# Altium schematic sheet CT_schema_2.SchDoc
size 401 x 230 mm
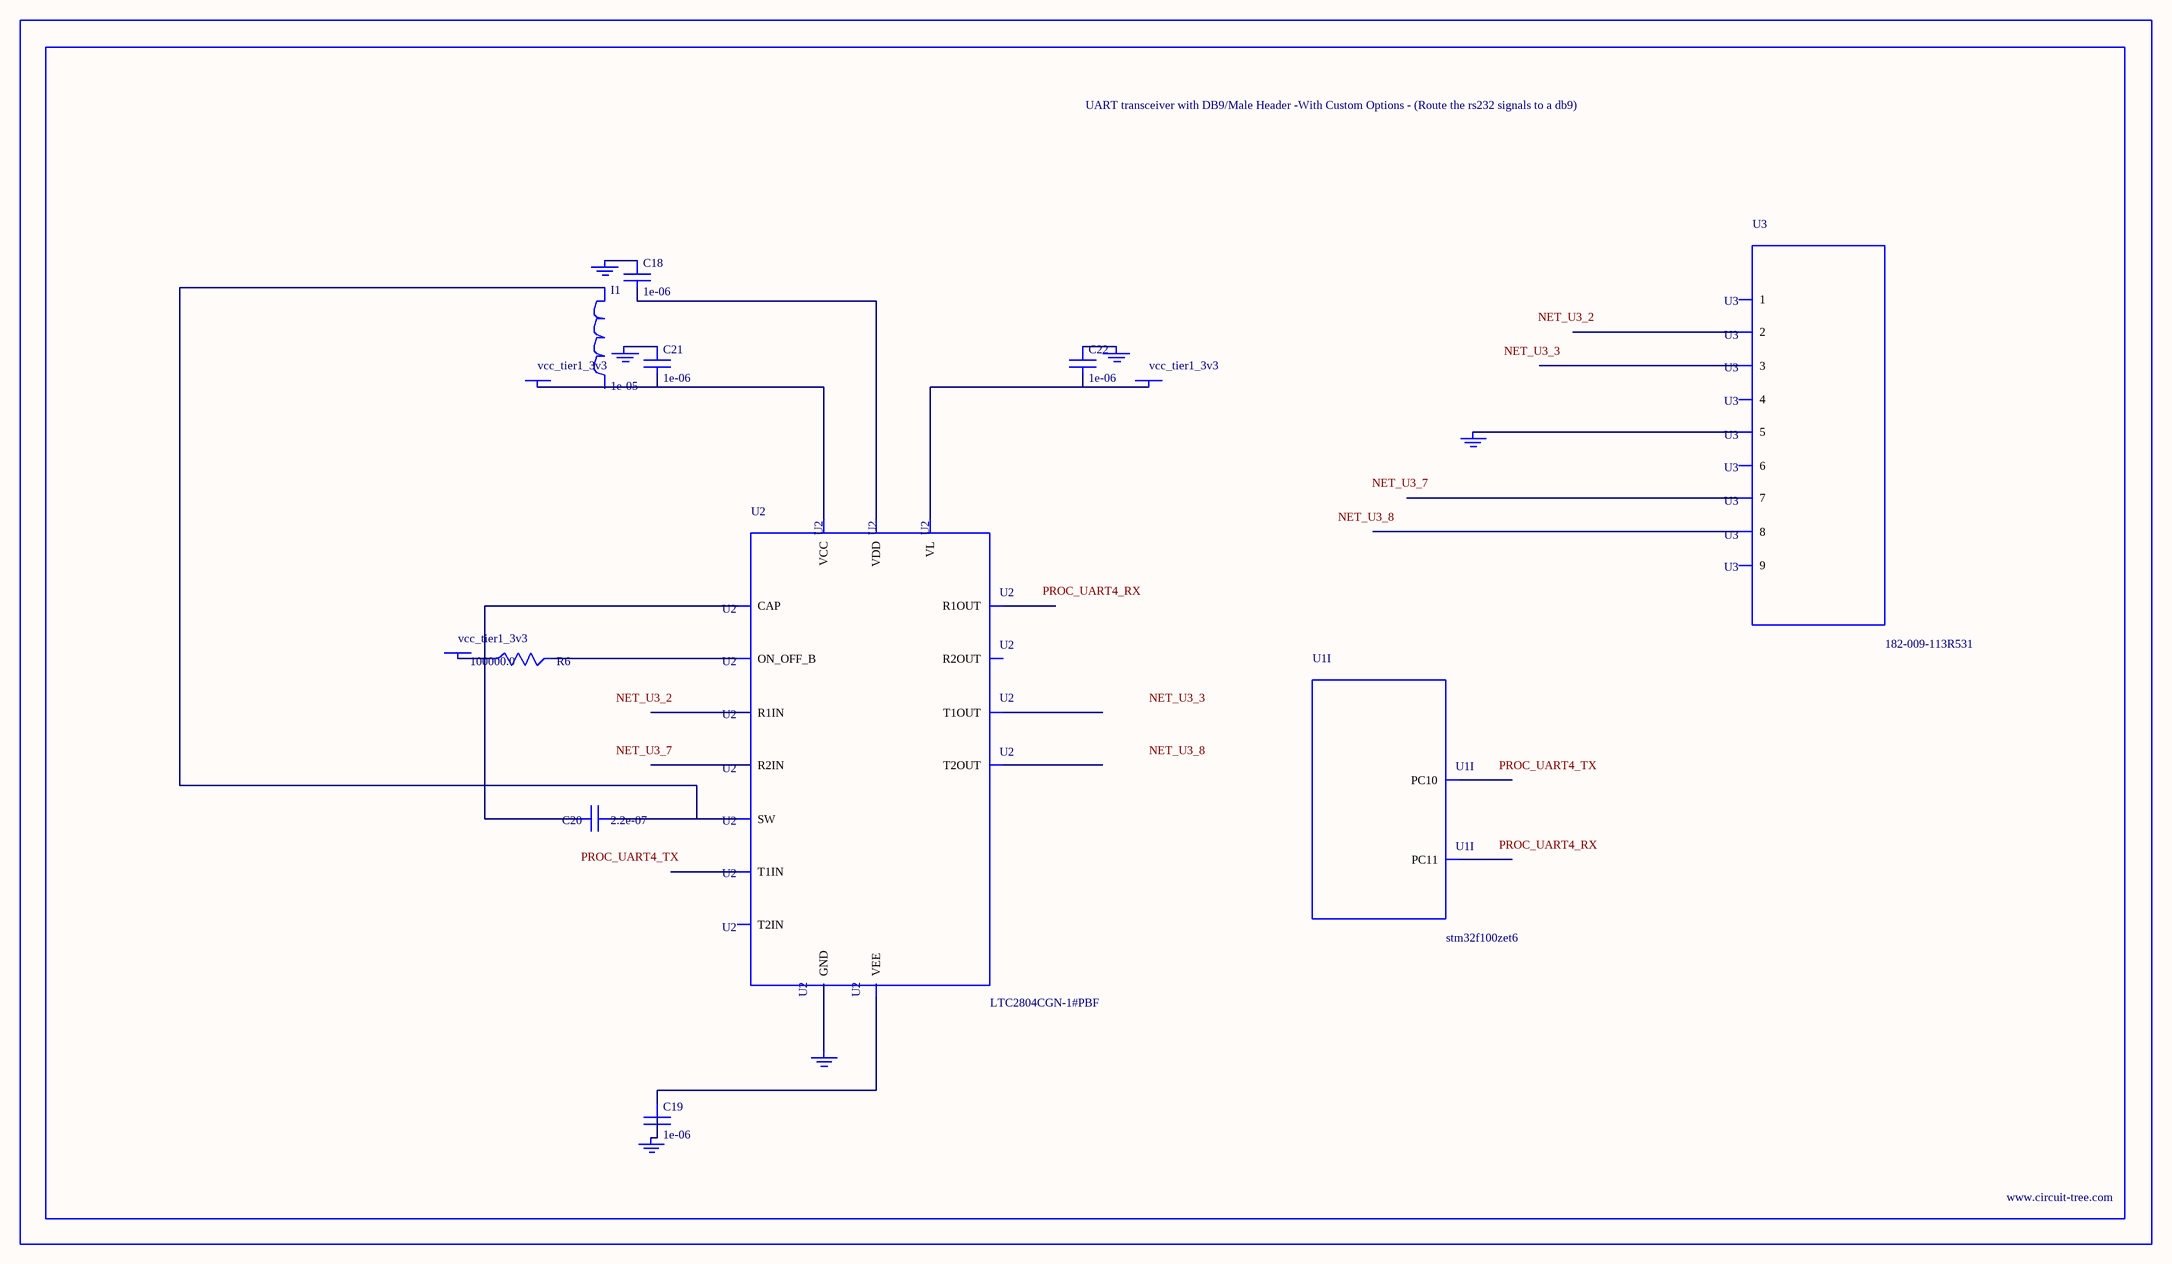
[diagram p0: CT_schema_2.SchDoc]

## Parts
BORDER1  (no value)
C18  1e-06  [C0603]
C19  1e-06  [C0603]
C20  2.2e-07  [C0603]
C21  1e-06  [C0603]
C22  1e-06  [C0603]
GND_INSTANCE_1_0  (no value)
GND_INSTANCE_1_1  (no value)
GND_INSTANCE_1_2  (no value)
GND_INSTANCE_1_3  (no value)
GND_INSTANCE_1_4  (no value)
GND_INSTANCE_1_5  (no value)
I1  1e-05  [L1210]
POWER_INSTANCE_1_0  vcc_tier1_3v3
POWER_INSTANCE_1_1  vcc_tier1_3v3
POWER_INSTANCE_1_2  vcc_tier1_3v3
R6  100000.0  [R0603]
U1  stm32f100zet6  [LQFP144]  (part I of 11)
U2  LTC2804CGN-1#PBF  [SSOP-16]
U3  182-009-113R531  [182-009-MALE]

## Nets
NetC18_1: C18.1 GND_INSTANCE_1_1.0(GND)
NetC18_2: C18.2 U2.6(VDD)
NetC19_1: C19.1 U2.9(VEE)
NetC19_2: C19.2 GND_INSTANCE_1_2.0(GND)
NetC20_1: C20.1 I1.1 U2.7(SW)
NetC20_2: C20.2 U2.10(CAP)
NetC21_1: C21.1 GND_INSTANCE_1_0.0(GND)
NetC21_2: C21.2 POWER_INSTANCE_1_0.0(PWR) U2.5(VCC)
NetC22_1: C22.1 GND_INSTANCE_1_3.0(GND)
NetC22_2: C22.2 POWER_INSTANCE_1_2.0(PWR) U2.12(VL)
NetGND_INSTANCE_1_4_0: GND_INSTANCE_1_4.0(GND) U2.8(GND)
NetGND_INSTANCE_1_5_0: GND_INSTANCE_1_5.0(GND) U3.5
NetPOWER_INSTANCE_1_1_0: POWER_INSTANCE_1_1.0(PWR) R6.1
NetR6_2: R6.2 U2.11(ON_OFF_B)

Not connected (* = marked no-connect by the designer): I1 2; U1 111(PC10) 112(PC11); U2 1(R1IN) 2(R2IN) 3(T1OUT) 4(T2OUT) 13(T2IN) 14(T1IN) 15(R2OUT) 16(R1OUT); U3 1 2 3 4 6 7 8 9

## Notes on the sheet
- Labels drawn without touching a wire or pin: NET_U3_2, NET_U3_3, NET_U3_7, NET_U3_8, PROC_UART4_RX, PROC_UART4_TX

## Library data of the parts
BORDER1 = BORDER_PAGE1
C18 C19 C21 C22 = C0603C105K3RACTU
C20 = C0603C224K3RAC
GND_INSTANCE_1_0-GND_INSTANCE_1_5 = GND
I1 = CBC3225T100MR
POWER_INSTANCE_1_0-POWER_INSTANCE_1_2 = PWR
R6 = RC0603JR-07100KL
